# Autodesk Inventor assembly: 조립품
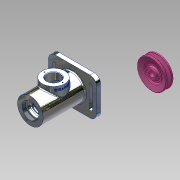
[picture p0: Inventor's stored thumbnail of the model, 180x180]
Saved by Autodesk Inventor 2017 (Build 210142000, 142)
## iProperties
Part Number: 조립품
Material: 일반
Document SubType Name: Assembly
Designer: user
Author: user
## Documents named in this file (3)
- C:\Users\user\Desktop\710706V1029_정익수\조립품.iam
- C:\Users\user\Desktop\710706V1029_정익수\본체.ipt
- C:\Users\user\Desktop\710706V1029\V-벨트풀리.ipt
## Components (1 placed, 1 different names)
1. V-벨트풀리:1
